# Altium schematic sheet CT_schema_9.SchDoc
size 274 x 160 mm
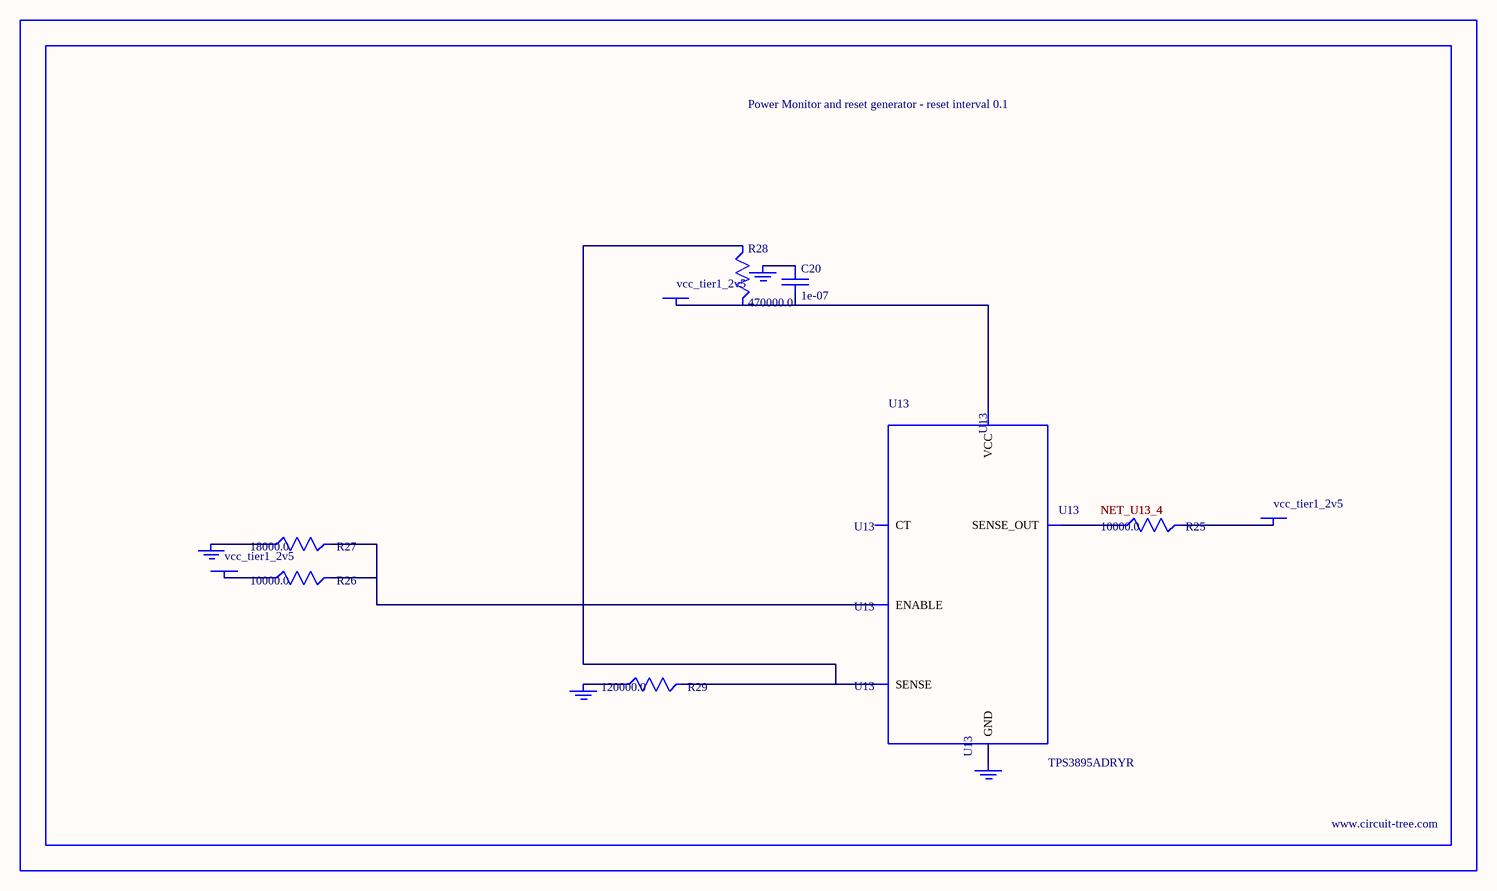
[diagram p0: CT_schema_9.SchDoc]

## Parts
BORDER8  (no value)
C20  1e-07  [C0402]
GND_INSTANCE_8_0  (no value)
GND_INSTANCE_8_1  (no value)
GND_INSTANCE_8_2  (no value)
GND_INSTANCE_8_3  (no value)
POWER_INSTANCE_8_0  vcc_tier1_2v5
POWER_INSTANCE_8_1  vcc_tier1_2v5
POWER_INSTANCE_8_2  vcc_tier1_2v5
R25  10000.0  [R0603]
R26  10000.0  [R0603]
R27  18000.0  [R0603]
R28  470000.0  [R0603]
R29  120000.0  [R0603]
U13  TPS3895ADRYR  [SON-6]

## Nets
NetC20_1: C20.1 GND_INSTANCE_8_2.0(GND)
NetC20_2: C20.2 POWER_INSTANCE_8_2.0(PWR) R28.2 U13.6(VCC)
NetGND_INSTANCE_8_0_0: GND_INSTANCE_8_0.0(GND) R27.1
NetGND_INSTANCE_8_1_0: GND_INSTANCE_8_1.0(GND) R29.1
NetGND_INSTANCE_8_3_0: GND_INSTANCE_8_3.0(GND) U13.2(GND)
NetPOWER_INSTANCE_8_0_0: POWER_INSTANCE_8_0.0(PWR) R26.1
NetPOWER_INSTANCE_8_1_0: POWER_INSTANCE_8_1.0(PWR) R25.2
NetR25_1: R25.1 U13.4(SENSE_OUT)
NetR26_2: R26.2 R27.2 U13.1(ENABLE)
NetR28_1: R28.1 R29.2 U13.3(SENSE)

Not connected (* = marked no-connect by the designer): U13 5(CT)

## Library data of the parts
BORDER8 = BORDER_PAGE8
C20 = C0402C104K3RACTU
GND_INSTANCE_8_0-GND_INSTANCE_8_3 = GND
POWER_INSTANCE_8_0-POWER_INSTANCE_8_2 = PWR
R25 R26 = RC0603JR-0710KL
R27 = RC0603JR-0718KL
R28 = RC0603JR-07470KL
R29 = RC0603JR-07120KL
